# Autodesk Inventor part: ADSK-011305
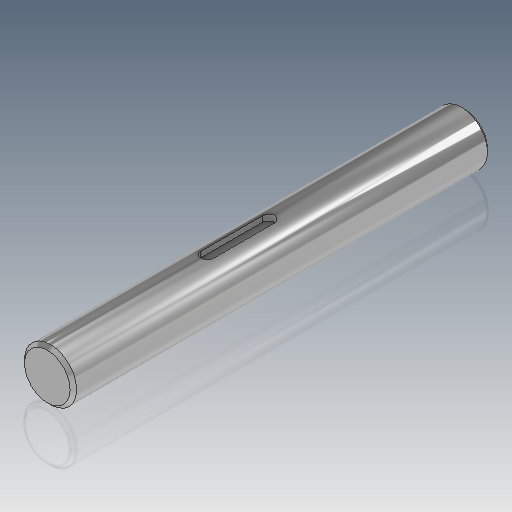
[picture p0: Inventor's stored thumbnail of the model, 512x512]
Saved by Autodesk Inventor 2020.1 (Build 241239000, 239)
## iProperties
Created: 1999-11
Part Number: ADSK-011305
Material: Acier doux
Description: SHFT-P,RC,AX,10,080,TAIL_SHAFT
Document SubType Name: Modeling
Designer: sspink
Density: 7.86 g/cm^3
Appearance: Chrom - poliert
Mass: 803.051 g
Surface Area: 172.83 cm^2
Volume: 102.169 cm^3
Control State: 0
Checked Out: False
Last Check In By: sspink
Last Check In Date: 1999-12-22
Master: False
Shininess: 0.0
Length Units: 11269
Angle Units: 11279
Time Units: 11290
Mass Units: 11283
Length Display Precision: 3
Angle Display Precision: 2
Compacted: True
Dimensions: 25,4x25,4x203,2 mm
Mass: 0,803 kg
DocNumber: ADSK-011305.ipt
Folder: 01 - Themengebiete\Simplification\01 - Packaging machine\
VDS_Category: 3D Komponenten
Density: 0.0
Volumn: 0.0
Area: 0.0
PropertySet Name: Model Information
Author: sspink
Revision Number: -
Title: shaft
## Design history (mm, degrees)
node "Solide1"
  node "Extrusion1" dims "d0" = 203.2, "d1" = 0
  node "Chamfer1" dims "d10" = 1.5875, "d11" = 1.5875, "d16" = 45 deg
workaxis "Work Axis1"
workplane "Work Plane2"
workplane "Work Plane4"
workplane "Arbeitsebene5"
sketch "Skizze4"
  geometry: L1 (0, 24)-(0, -6); L2 (-3, 24)-(-3, -6); L3 (3, -6)-(3, 24); L4 (0, -142.24)-(0, 142.24) reference; A1 r 3 centre (0, 24) between (3, 24) and (-3, 24); A2 r 3 centre (0, -6) between (-3, -6) and (3, -6); 2 further points
  constraints: 8 end point, 4 point on circle, 4 tangent, 2 centre point, 1 coincident, 1 collinear, 1 parallel, 1 vertical
  dimensions: "d17" = 6 distance between parallel lines of L2 L3; "d18" = 30 distance of L1.start L1.end; "d21" = 6 distance of L1.end point (0, 0)
extrude "Extrusion4" cut sketch "Skizze4" distance "d19" = 3; taper "d20" = 0 deg
node "Corps solides"
node "Corps surfaciques"
sketch "Sketch1"
  geometry: C1 r 12.7 at (0, 0)
  constraints: 1 centre point, 1 other
  dimensions: "d12" = 25.4 diameter of C1
other parameters: "d13" = 90 deg, "d15" = -101.6
